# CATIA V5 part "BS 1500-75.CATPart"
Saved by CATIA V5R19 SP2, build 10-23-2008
Part number: BS 1500-75
Bounding box of the stored display mesh (mm): x -31.459 to 31.459, y -31.459 to 31.459, z 0 to 194
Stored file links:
  C:\Users\Bora\Desktop\3D Katı model\BS serisi\BS 1500\BS 1500-75.CATPart
  C:\Program Files\Dassault Systemes\B19\intel_a\reffiles\standard\MetricThickPitch.txt
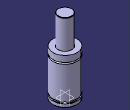
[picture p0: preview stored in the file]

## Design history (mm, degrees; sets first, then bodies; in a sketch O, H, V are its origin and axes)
Body1 (main body)
  Sketch1 on yz-plane, origin (0, 0, 0), H (0, 1, 0), V (0, 0, 1)
    point P1 (31.5, 102)
    point P2 (31.5, 98)
    point P3 (31.5, 102)
    point P7 (18, 193)
    point P9 (18, 193)
    point P14 (31.5, 98)
    arc A1 centre (31.5, 100) radius 2 from (31.5, 102) to (31.5, 98) ccw
    line L1 (31.5, 102) -> (31.5, 118)
    line L2 (31.5, 0) -> (31.5, 8)
    arc A2 centre (17, 193) radius 1 from (18, 193) to (17, 194) ccw
    line L3 (18, 193) -> (18, 118)
    line L4 (29, 13) -> (29, 8)
    line L5 (31.5, 13) -> (31.5, 98)
    line L6 (17, 194) -> (0, 194)
    point P15 (0, 194)
    line L7 (18, 118) -> (31.5, 118)
    line L8 (0, 0) -> (31.5, 0)
    line L9 (29, 13) -> (31.5, 13)
    line L10 (29, 8) -> (31.5, 8)
    coincidence: P15 V, P1 P3, P2 P14, P7 P9
    tangency: L6 A2
    horizontal: L7 H, L8 H, L9 H, L10 H
  Shaft1: profile Sketch1, axis Sketch1.V, angle 360
  Sketch2 on face of Shaft1 from Sketch1.L8, origin (0, 0, 0), H (1, 0, 0), V (0, -1, 0)
    point P1 (10, 0)
    distance P1 V = 10
  Hole1: placed by Sketch2, at (10, 0, 0) direction (0, 0, 1), diameter 6.647, depth 5, threaded "M8", thread diameter 8, thread depth 5, pitch 1.25
  CircPattern1: of Hole1, instances 2, angular step 180, axis from xy-plane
